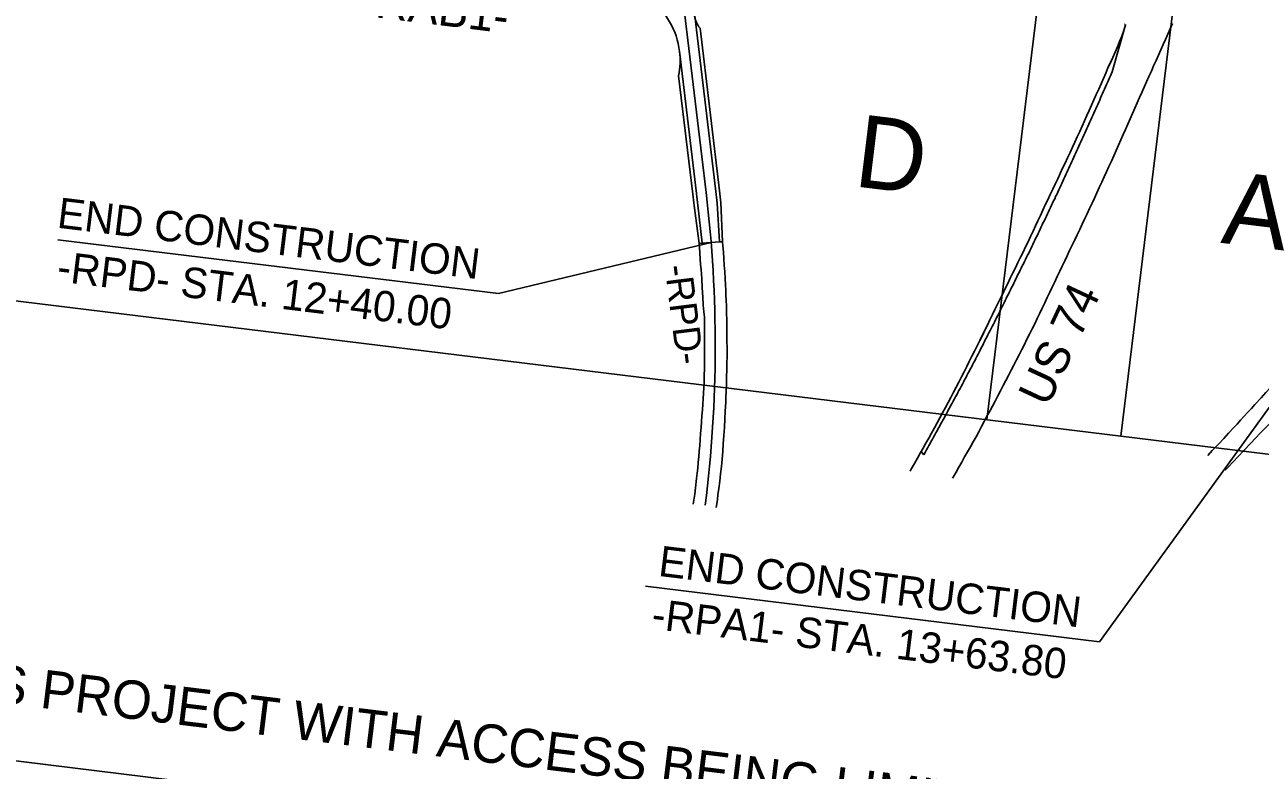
# Model space of a CAD drawing. Extents: x 1756435 to 1766932, y 416863 to 426859.
# Drawn here: x 1761555 to 1762835, y 423038 to 423810 of the extents above; entities that cross this region are included whole.
import ezdxf

# ---------------------------------------------------------------- set-up
doc = ezdxf.new("R2010")
doc.units = 0
for name, color, linetype in [('Exist Roads EOP', 7, 'Continuous'), ('Prop Dimension Text', 7, 'Continuous'), ('Prop Horizontal Alignment', 7, 'Continuous'), ('Prop Horizontal Alignment Station Label', 7, 'Continuous'), ('Prop Rem of Exist Asph Pvmt', 7, 'Continuous'), ('Prop Shade Light', 7, 'Continuous'), ('Sheet Data Field CELL', 7, 'Continuous'), ('Sheet Plan CELL', 7, 'Continuous'), ('Sheet Title CELL', 7, 'Continuous')]:
    doc.layers.add(name, color=color, linetype=linetype)

msp = doc.modelspace()

# ---------------------------------------------------------------- linework, layer by layer
at = {"layer": 'Exist Roads EOP'}
for points in [[(1762744, 423811.4), (1762741.6, 423805.9), (1762739.2, 423800.4), (1762736.7, 423794.9), (1762734.3, 423789.5), (1762731.8, 423784), (1762729.4, 423778.5), (1762727, 423773), (1762724.5, 423767.5), (1762722.1, 423762.1), (1762719.6, 423756.6), (1762717.2, 423751.1), (1762714.8, 423745.6), (1762712.3, 423740.1), (1762709.9, 423734.6), (1762707.5, 423729.2), (1762705, 423723.7), (1762702.6, 423718.2), (1762700.2, 423712.7), (1762697.7, 423707.2), (1762695.3, 423701.7), (1762692.9, 423696.3), (1762690.4, 423690.8), (1762688, 423685.3), (1762685.6, 423679.8), (1762683.1, 423674.3), (1762680.7, 423668.9), (1762678.2, 423663.4), (1762675.7, 423657.9), (1762673.2, 423652.5), (1762670.7, 423647), (1762668.2, 423641.6), (1762665.7, 423636.1), (1762663.2, 423630.6), (1762660.7, 423625.2), (1762658.2, 423619.8), (1762655.6, 423614.4), (1762653, 423608.9), (1762650.4, 423603.5), (1762647.9, 423598.1), (1762645.3, 423592.7), (1762642.7, 423587.3), (1762640.1, 423581.9), (1762637.5, 423576.4), (1762635, 423571), (1762632.4, 423565.6), (1762629.8, 423560.2), (1762627.2, 423554.8), (1762624.7, 423549.4), (1762622.1, 423543.9), (1762619.5, 423538.5), (1762616.9, 423533.1), (1762614.3, 423527.7), (1762611.8, 423522.3), (1762609.2, 423516.8), (1762606.6, 423511.4), (1762604, 423506), (1762601.4, 423500.6), (1762598.7, 423495.3), (1762596, 423489.9), (1762593.3, 423484.5), (1762590.6, 423479.2), (1762588, 423473.8), (1762585.3, 423468.4), (1762582.6, 423463.1), (1762579.8, 423457.8), (1762577, 423452.4), (1762574.3, 423447.1), (1762571.5, 423441.8), (1762568.7, 423436.5), (1762565.9, 423431.2), (1762563.2, 423425.8), (1762560.4, 423420.5), (1762557.6, 423415.2), (1762554.7, 423409.9), (1762551.9, 423404.7), (1762549.1, 423399.4), (1762546.2, 423394.1), (1762543.4, 423388.8), (1762540.6, 423383.5), (1762537.6, 423378.3), (1762534.7, 423373.1), (1762531.7, 423367.8), (1762528.7, 423362.6), (1762525.8, 423357.4), (1762522.8, 423352.2), (1762519.9, 423347), (1762516.9, 423341.7), (1762516.3, 423340.6)], [(1762472.3, 423348), (1762473.8, 423350.8), (1762476.8, 423356), (1762479.8, 423361.2), (1762482.7, 423366.4), (1762485.7, 423371.6), (1762488.6, 423376.8), (1762491.6, 423382.1), (1762494.5, 423387.3), (1762497.4, 423392.6), (1762500.3, 423397.8), (1762503.2, 423403.1), (1762506, 423408.4), (1762508.8, 423413.7), (1762511.6, 423419), (1762514.4, 423424.3), (1762517.2, 423429.6), (1762520, 423434.9), (1762522.8, 423440.2), (1762525.6, 423445.5), (1762528.3, 423450.9), (1762530.9, 423456.2), (1762533.6, 423461.6), (1762536.3, 423467), (1762539, 423472.3), (1762541.7, 423477.7), (1762544.4, 423483.1), (1762547.1, 423488.4), (1762549.7, 423493.8), (1762552.3, 423499.2), (1762555, 423504.6), (1762557.6, 423510), (1762560.2, 423515.4), (1762562.9, 423520.8), (1762565.5, 423526.2), (1762568.2, 423531.6), (1762570.8, 423536.9), (1762573.4, 423542.3), (1762576, 423547.7), (1762578.7, 423553.1), (1762581.3, 423558.5), (1762583.9, 423563.9), (1762586.6, 423569.3), (1762589.2, 423574.7), (1762591.8, 423580.1), (1762594.5, 423585.5), (1762597, 423590.9), (1762599.6, 423596.3), (1762602.1, 423601.8), (1762604.7, 423607.2), (1762607.2, 423612.6), (1762609.8, 423618), (1762612.3, 423623.5), (1762614.9, 423628.9), (1762617.4, 423634.3), (1762620, 423639.8), (1762622.6, 423645.2), (1762625.1, 423650.6), (1762627.7, 423656), (1762630.2, 423661.5), (1762632.8, 423666.9), (1762635.3, 423672.3), (1762637.9, 423677.8), (1762640.4, 423683.2), (1762643, 423688.6), (1762645.4, 423694.1), (1762647.9, 423699.6), (1762650.4, 423705), (1762652.8, 423710.5), (1762655.3, 423716), (1762657.8, 423721.4), (1762660.2, 423726.9), (1762662.7, 423732.4), (1762665.1, 423737.9), (1762667.6, 423743.3), (1762670, 423748.8), (1762672.4, 423754.3), (1762674.8, 423759.8), (1762677.2, 423765.3), (1762679.7, 423770.8), (1762682.1, 423776.3), (1762684.5, 423781.8), (1762686.9, 423787.3), (1762689.2, 423792.8), (1762691.5, 423798.4), (1762693.5, 423804), (1762695.5, 423810.1), (1762694.3, 423811)], [(1762253.8, 423583.5), (1762254.1, 423579.6), (1762254.6, 423573.6), (1762255, 423567.7), (1762255.4, 423562), (1762255.8, 423556.6), (1762256.5, 423546.9), (1762257.1, 423537.7), (1762257.5, 423528.3), (1762258, 423519.7), (1762258.8, 423512.9), (1762259.4, 423507.2), (1762259.5, 423502), (1762259.3, 423494.8), (1762259.3, 423489.5), (1762259.3, 423483), (1762259.3, 423475.9), (1762259.3, 423468.7), (1762259.3, 423461.4), (1762259.3, 423454.1), (1762259.2, 423447), (1762259, 423440.3), (1762258.7, 423434.2), (1762258.4, 423428.5), (1762258, 423422.9), (1762257.6, 423417.2), (1762257.2, 423411.3), (1762256.7, 423405.3), (1762256.3, 423399.1), (1762255.9, 423393), (1762255.4, 423386.8), (1762254.9, 423380.6), (1762254.4, 423374.5), (1762253.9, 423368.5), (1762253.4, 423362.6), (1762252.9, 423356.8), (1762252.4, 423351.1), (1762251.8, 423345.7), (1762251.2, 423340.4), (1762250.1, 423330.8), (1762249.2, 423324), (1762248.7, 423319.9), (1762248.1, 423315.9), (1762247.8, 423313.9)], [(1762271.6, 423310.4), (1762272.1, 423314.1), (1762272.7, 423318.5), (1762273.3, 423323.4), (1762274.1, 423330), (1762275.1, 423337.5), (1762276, 423345.2), (1762276.9, 423352.8), (1762277.6, 423360.4), (1762278.2, 423368.1), (1762278.8, 423376.3), (1762279.4, 423384.8), (1762280, 423393.2), (1762280.5, 423401.6), (1762280.9, 423409.9), (1762281.3, 423419.2), (1762281.5, 423424.5), (1762281.7, 423430.3), (1762282, 423436.1), (1762282.3, 423445.7), (1762282.5, 423452.9), (1762282.6, 423459.7), (1762282.7, 423466.5), (1762282.7, 423474.5), (1762282.6, 423483.6), (1762282.5, 423491.2), (1762282.5, 423497.2), (1762282.4, 423504.1), (1762282.2, 423511.9), (1762282, 423518.8), (1762281.8, 423524.8), (1762281.6, 423530.1), (1762281.4, 423535.2), (1762281.1, 423540.9), (1762280.7, 423547.4), (1762280.3, 423554.2), (1762279.8, 423561.2), (1762279.3, 423568), (1762278.9, 423574.6), (1762278.3, 423581.3), (1762277.9, 423585.4)], [(1762780.5, 423364.2), (1762785.2, 423369.2), (1762791.9, 423376.3), (1762797, 423381.8), (1762802, 423387.1), (1762807.5, 423393.1), (1762810.8, 423396.7), (1762814.5, 423400.7), (1762818.3, 423404.8), (1762822, 423408.9), (1762825.7, 423412.9), (1762829.3, 423416.8), (1762835.8, 423423.9), (1762840.8, 423429.4), (1762845.1, 423434.2), (1762849.7, 423439.3), (1762854.6, 423444.8), (1762859.9, 423450.7), (1762865.3, 423457), (1762870.7, 423463.4), (1762873.9, 423467.2)], [(1762798.4, 423348.9), (1762801.2, 423351.8), (1762807, 423357.9), (1762811.6, 423362.8), (1762818.2, 423369.7), (1762824.3, 423376.1), (1762830.7, 423382.8), (1762834.5, 423386.8), (1762838.8, 423391.3), (1762843.7, 423396.3), (1762848.6, 423401.4), (1762853.4, 423406.3), (1762857.9, 423411), (1762862.2, 423415.6), (1762866.4, 423420), (1762870.6, 423424.5), (1762874.8, 423429), (1762879, 423433.5), (1762883.1, 423438), (1762887.2, 423442.5), (1762891.3, 423447.1), (1762894.2, 423450.1)]]:
    msp.add_lwpolyline(points, dxfattribs=at)
at = {"layer": 'Prop Horizontal Alignment'}
msp.add_line((1762238.7, 423822.9), (1762261.1, 423636.4), dxfattribs=at)
msp.add_arc((1760945.5, 423478.5), 1325, 352.8059, 6.8416, dxfattribs=at)
at = {"layer": 'Prop Horizontal Alignment Station Label'}
for p, q in [((1761589.8, 423587.5), (1762045.9, 423531.7)), ((1762045.9, 423531.7), (1762266.3, 423584.5)), ((1762879.3, 423462.7), (1762668.5, 423171.2)), ((1762198.4, 423228.7), (1762668.5, 423171.2))]:
    msp.add_line(p, q, dxfattribs=at)
at = {"layer": 'Prop Rem of Exist Asph Pvmt'}
for p, q in [((1762681.5, 423761.4), (1762695.5, 423810.1)), ((1762695.5, 423810.1), (1762693.5, 423804)), ((1762483.7, 423368.2), (1762486.4, 423364.7))]:
    msp.add_line(p, q, dxfattribs=at)
for points in [[(1762693.5, 423804), (1762691.5, 423798.4), (1762689.2, 423792.8), (1762686.9, 423787.3), (1762684.5, 423781.8), (1762682.1, 423776.3), (1762679.6, 423770.8), (1762677.2, 423765.3), (1762674.8, 423759.8), (1762672.4, 423754.3), (1762670, 423748.8), (1762667.6, 423743.3), (1762665.1, 423737.9), (1762662.7, 423732.4), (1762660.2, 423726.9), (1762657.8, 423721.4), (1762655.3, 423716), (1762652.8, 423710.5), (1762650.4, 423705), (1762647.9, 423699.6), (1762645.4, 423694.1), (1762643, 423688.6), (1762640.4, 423683.2), (1762637.9, 423677.8), (1762635.3, 423672.3), (1762632.8, 423666.9), (1762630.2, 423661.5), (1762627.7, 423656), (1762625.1, 423650.6), (1762622.6, 423645.2), (1762620, 423639.8), (1762617.4, 423634.3), (1762614.9, 423628.9), (1762612.3, 423623.5), (1762609.8, 423618), (1762607.2, 423612.6), (1762604.7, 423607.2), (1762602.1, 423601.8), (1762599.6, 423596.3), (1762597, 423590.9), (1762594.5, 423585.5), (1762591.8, 423580.1), (1762589.2, 423574.7), (1762586.6, 423569.3), (1762583.9, 423563.9), (1762581.3, 423558.5), (1762578.7, 423553.1), (1762576, 423547.7), (1762573.4, 423542.3), (1762570.8, 423536.9), (1762568.2, 423531.6), (1762565.5, 423526.2), (1762562.9, 423520.8), (1762560.2, 423515.4), (1762557.6, 423510), (1762555, 423504.6), (1762552.3, 423499.2), (1762549.7, 423493.8), (1762547, 423488.4), (1762544.4, 423483.1), (1762541.7, 423477.7), (1762539, 423472.3), (1762536.3, 423467), (1762533.6, 423461.6), (1762530.9, 423456.2), (1762528.3, 423450.9), (1762525.6, 423445.5), (1762522.8, 423440.2), (1762520, 423434.9), (1762517.2, 423429.6), (1762514.4, 423424.3), (1762511.6, 423419), (1762508.8, 423413.7), (1762506, 423408.4), (1762503.2, 423403.1), (1762500.3, 423397.8), (1762497.4, 423392.6), (1762494.5, 423387.3), (1762491.6, 423382.1), (1762488.6, 423376.8), (1762485.7, 423371.6), (1762483.7, 423368.2)], [(1762486.4, 423364.7), (1762488.2, 423367.9), (1762489.4, 423370.1), (1762490.6, 423372.3), (1762491.8, 423374.5), (1762493, 423376.7), (1762494.2, 423378.9), (1762495.4, 423381), (1762496.6, 423383.2), (1762497.9, 423385.4), (1762499.1, 423387.6), (1762500.3, 423389.8), (1762501.5, 423392), (1762502.7, 423394.2), (1762503.9, 423396.4), (1762505.1, 423398.5), (1762506.3, 423400.7), (1762507.5, 423402.9), (1762508.7, 423405.1), (1762509.9, 423407.3), (1762511, 423409.5), (1762512.2, 423411.7), (1762513.4, 423413.9), (1762514.6, 423416.1), (1762515.8, 423418.3), (1762517, 423420.5), (1762518.2, 423422.7), (1762519.4, 423424.8), (1762520.6, 423427), (1762521.8, 423429.2), (1762522.9, 423431.4), (1762524.1, 423433.5), (1762525.2, 423435.7), (1762526.4, 423437.9), (1762527.6, 423440.2), (1762528.7, 423442.4), (1762529.9, 423444.6), (1762531.1, 423446.8), (1762532.2, 423449), (1762533.4, 423451.2), (1762534.5, 423453.4), (1762535.7, 423455.7), (1762536.9, 423457.9), (1762538, 423460.1), (1762539.2, 423462.3), (1762540.3, 423464.5), (1762541.4, 423466.7), (1762542.6, 423468.9), (1762543.7, 423471.1), (1762544.8, 423473.3), (1762546, 423475.6), (1762547.1, 423477.8), (1762548.3, 423480), (1762549.4, 423482.2), (1762550.5, 423484.5), (1762551.7, 423486.7), (1762552.8, 423488.9), (1762553.9, 423491.1), (1762555.1, 423493.4), (1762556.2, 423495.6), (1762557.4, 423497.8), (1762558.5, 423500), (1762559.6, 423502.2), (1762560.8, 423504.5), (1762561.9, 423506.6), (1762563, 423508.9), (1762564.1, 423511.1), (1762565.2, 423513.3), (1762566.3, 423515.6), (1762567.4, 423517.8), (1762568.5, 423520), (1762569.6, 423522.3), (1762570.7, 423524.5), (1762571.8, 423526.8), (1762572.9, 423529), (1762574.1, 423531.2), (1762575.2, 423533.5), (1762576.3, 423535.7), (1762577.4, 423538), (1762578.5, 423540.2), (1762579.6, 423542.4), (1762580.7, 423544.7), (1762581.8, 423546.9), (1762582.9, 423549.2), (1762584, 423551.4), (1762585.2, 423553.6), (1762586.3, 423555.9), (1762587.4, 423558.1), (1762588.5, 423560.4), (1762589.6, 423562.6), (1762590.7, 423564.8), (1762591.8, 423567.1), (1762592.9, 423569.3), (1762594, 423571.5), (1762595.1, 423573.7), (1762596.1, 423576), (1762597.2, 423578.2), (1762598.3, 423580.5), (1762599.4, 423582.7), (1762600.5, 423585), (1762601.5, 423587.2), (1762602.6, 423589.5), (1762603.7, 423591.7), (1762604.8, 423594), (1762605.9, 423596.2), (1762607, 423598.5), (1762608, 423600.7), (1762609.1, 423603), (1762610.2, 423605.3), (1762611.3, 423607.5), (1762612.4, 423609.8), (1762613.5, 423612), (1762614.5, 423614.3), (1762615.6, 423616.5), (1762616.7, 423618.8), (1762617.8, 423621), (1762618.8, 423623.2), (1762619.9, 423625.4), (1762620.9, 423627.7), (1762622, 423630), (1762623, 423632.2), (1762624.1, 423634.5), (1762625.1, 423636.8), (1762626.2, 423639), (1762627.2, 423641.3), (1762628.3, 423643.6), (1762629.3, 423645.8), (1762630.4, 423648.1), (1762631.4, 423650.4), (1762632.5, 423652.6), (1762633.5, 423654.9), (1762634.6, 423657.2), (1762635.6, 423659.4), (1762636.7, 423661.7), (1762637.7, 423664), (1762638.8, 423666.2), (1762639.8, 423668.5), (1762640.8, 423670.7), (1762641.9, 423673), (1762642.9, 423675.3), (1762643.9, 423677.6), (1762645, 423679.8), (1762646, 423682.1), (1762647, 423684.4), (1762648.1, 423686.7), (1762649.1, 423688.9), (1762650.1, 423691.2), (1762651.2, 423693.5), (1762652.2, 423695.8), (1762653.2, 423698), (1762654.3, 423700.3), (1762655.3, 423702.6), (1762656.3, 423704.9), (1762657.4, 423707.1), (1762658.4, 423709.4), (1762659.5, 423711.7), (1762660.5, 423714), (1762661.5, 423716.2), (1762662.5, 423718.5), (1762663.6, 423720.8), (1762664.6, 423723), (1762665.6, 423725.3), (1762666.6, 423727.5), (1762667.6, 423729.8), (1762668.6, 423732.1), (1762669.6, 423734.4), (1762670.6, 423736.7), (1762671.6, 423739), (1762672.6, 423741.3), (1762673.6, 423743.5), (1762674.6, 423745.8), (1762675.6, 423748.1), (1762676.6, 423750.4), (1762677.7, 423752.7), (1762678.7, 423755), (1762679.7, 423757.3), (1762681.5, 423761.4)]]:
    msp.add_lwpolyline(points, dxfattribs=at)
at = {"layer": 'Prop Shade Light'}
for p, q in [((1762249.2, 423819.4), (1762271, 423637.5)), ((1762271, 423637.5), (1762249.2, 423819.4)), ((1762275, 423638), (1762254.8, 423806.4)), ((1762251.2, 423635.2), (1762233.5, 423782.6)), ((1762233.5, 423782.6), (1762251.2, 423635.2)), ((1762232.5, 423757.3), (1762247.2, 423634.7)), ((1762248.6, 423622.8), (1762253.8, 423583.5)), ((1762256.8, 423583.8), (1762252.6, 423623.2)), ((1762252.6, 423623.2), (1762256.8, 423583.8)), ((1762272.4, 423625.4), (1762275, 423585.2)), ((1762275, 423585.2), (1762272.4, 423625.4)), ((1762277.9, 423585.4), (1762276.4, 423625.9)), ((1762253.8, 423583.5), (1762256.8, 423583.8)), ((1762256.8, 423583.8), (1762275, 423585.2)), ((1762275, 423585.2), (1762277.9, 423585.4))]:
    msp.add_line(p, q, dxfattribs=at)
for centre, radius, start, end in [((1762154.1, 423773), 80, 6.8415, 53.4393), ((1762274, 423822.4), 25, 186.8416, 219.7015), ((1762154.1, 423773), 80, 348.6468, 6.8415), ((1760945.5, 423478.5), 1311, 6.3184, 6.8416), ((1760945.5, 423478.5), 1315, 6.3184, 6.8416), ((1760945.5, 423478.5), 1315, 6.3184, 6.8416), ((1760945.5, 423478.5), 1335, 6.3184, 6.8416), ((1760945.5, 423478.5), 1335, 6.3184, 6.8416), ((1760945.5, 423478.5), 1339, 6.3184, 6.8416)]:
    msp.add_arc(centre, radius, start, end, dxfattribs=at)
at = {"layer": 'Sheet Plan CELL'}
msp.add_lwpolyline([(1761201.5, 423566.5), (1761329, 424608.7), (1762817.9, 424426.5), (1762690.4, 423384.3)], close=True, dxfattribs=at)
for points in [[(1762817.9, 424426.5), (1764168.3, 424261.3), (1764040.8, 423219), (1762690.4, 423384.3)], [(1762551.8, 423401.2), (1762661.1, 424294.5)]]:
    msp.add_lwpolyline(points, dxfattribs=at)
at = {"layer": 'Sheet Title CELL'}
msp.add_line((1760322.1, 423197.7), (1766013.7, 422501.2), dxfattribs=at)

# ---------------------------------------------------------------- texts
at = {"layer": 'Prop Dimension Text'}
for s, p in [('D', (1762412.8, 423643)), ('A', (1762793.2, 423584.4))]:
    msp.add_text(s, height=75, rotation=353.0234, dxfattribs=at).set_placement(p)
at = {"layer": 'Sheet Data Field CELL'}
for s, height, rotation, p in [('-RAB1-', 35, 353.0234, (1761902.3, 423819.7)), ('-RPD-', 28, 277.1512, (1762218.1, 423560.2)), ('US 74', 35, 64.9836, (1762614.9, 423413.4)), ('THIS IS A PARTIAL CONTROLLED ACCESS PROJECT WITH ACCESS BEING LIMITED TO POINTS SHOWN ON THE PLANS.', 39.75, 353.0234, (1760479.7, 423236.6))]:
    msp.add_text(s, height=height, rotation=rotation, dxfattribs=at).set_placement(p)
at = {"layer": 'Sheet Plan CELL'}
for s, p in [('END CONSTRUCTION', (1761588.1, 423600.1)), ('-RPD- STA. 12+40.00', (1761587.9, 423544.5)), ('END CONSTRUCTION', (1762210.7, 423239.6)), ('-RPA1- STA. 13+63.80', (1762203.5, 423184.8))]:
    msp.add_text(s, height=31.5, rotation=353.0244, dxfattribs=at).set_placement(p)

doc.saveas('drawing.dxf')
